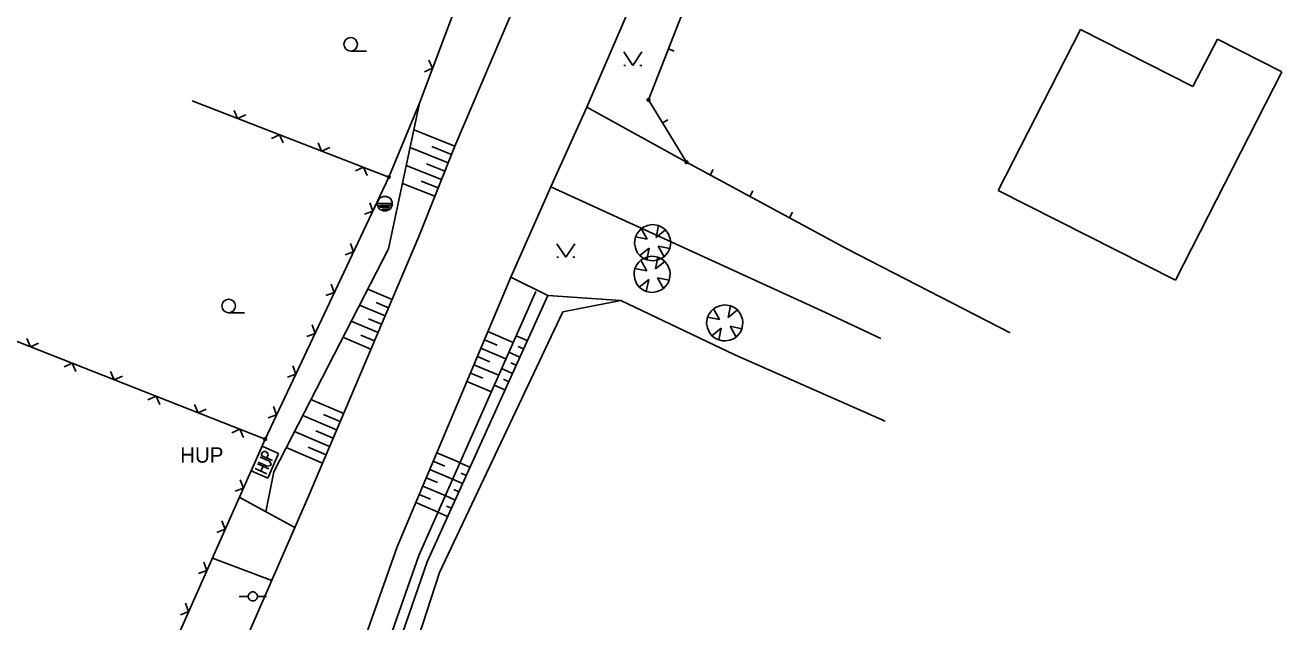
# Model space of a CAD drawing. Extents: x -559554 to -559082, y -1075950 to -1075150.
# Drawn here: x -559203.9 to -559134.2, y -1075319.9 to -1075286.8 of the extents above; entities that cross this region are included whole.
import ezdxf

# ---------------------------------------------------------------- set-up
doc = ezdxf.new("R2010")
doc.units = 0
doc.layers.add('kl', color=7, linetype='Continuous')
doc.layers.add('PF', color=7, linetype='Continuous')

msp = doc.modelspace()

# ---------------------------------------------------------------- linework, layer by layer
at = {"layer": 'kl'}
for p, q in [((-559182.05, -1075291.08), (-559175.25, -1075273.02)), ((-559180.09, -1075293.47), (-559173.73, -1075278.55)), ((-559172.77, -1075291.32), (-559167.67, -1075279.49)), ((-559164.97, -1075279.68), (-559169.34, -1075290.91)), ((-559185.866, -1075288.195), (-559184.991, -1075288.195)), ((-559170.716, -1075288.24), (-559170.216, -1075288.99)), ((-559170.216, -1075288.99), (-559169.716, -1075288.24)), ((-559168.233, -1075288.067), (-559167.907, -1075288.194)), ((-559181.323, -1075289.149), (-559181.527, -1075288.698)), ((-559170.716, -1075288.99), (-559170.616, -1075288.99)), ((-559169.816, -1075288.99), (-559169.716, -1075288.99)), ((-559181.773, -1075289.353), (-559181.323, -1075289.149)), ((-559183.75, -1075295.19), (-559194.672, -1075290.966)), ((-559183.77, -1075299.18), (-559182.05, -1075291.08)), ((-559183.75, -1075295.19), (-559182.05, -1075291.08)), ((-559169.395, -1075290.909), (-559169.384, -1075290.887)), ((-559169.306, -1075290.955), (-559169.395, -1075290.909)), ((-559169.385, -1075290.943), (-559169.34, -1075290.966)), ((-559169.384, -1075290.887), (-559169.295, -1075290.932)), ((-559169.372, -1075290.865), (-559169.339, -1075290.854)), ((-559169.283, -1075290.91), (-559169.372, -1075290.865)), ((-559169.34, -1075290.91), (-559167.23, -1075294.37)), ((-559169.34, -1075290.966), (-559169.306, -1075290.955)), ((-559169.339, -1075290.854), (-559169.294, -1075290.877)), ((-559169.295, -1075290.932), (-559169.283, -1075290.91)), ((-559192.344, -1075291.491), (-559192.144, -1075291.943)), ((-559192.144, -1075291.943), (-559191.691, -1075291.743)), ((-559174.76, -1075295.73), (-559172.77, -1075291.32)), ((-559167.23, -1075294.37), (-559172.77, -1075291.32)), ((-559168.559, -1075292.19), (-559168.26, -1075292.008)), ((-559189.812, -1075292.845), (-559190.265, -1075293.045)), ((-559189.612, -1075293.298), (-559189.812, -1075292.845)), ((-559180.09, -1075293.47), (-559182.365, -1075292.563)), ((-559187.68, -1075293.294), (-559187.48, -1075293.747)), ((-559187.48, -1075293.747), (-559187.028, -1075293.547)), ((-559180.46, -1075294.398), (-559182.575, -1075293.556)), ((-559182.09, -1075298.49), (-559180.09, -1075293.47)), ((-559180.275, -1075293.934), (-559181.372, -1075293.497)), ((-559180.83, -1075295.327), (-559182.786, -1075294.548)), ((-559180.645, -1075294.863), (-559181.663, -1075294.457)), ((-559167.285, -1075294.369), (-559167.274, -1075294.347)), ((-559167.196, -1075294.415), (-559167.285, -1075294.369)), ((-559167.275, -1075294.403), (-559167.23, -1075294.426)), ((-559167.274, -1075294.347), (-559167.185, -1075294.392)), ((-559167.262, -1075294.325), (-559167.229, -1075294.314)), ((-559167.173, -1075294.37), (-559167.262, -1075294.325)), ((-559167.23, -1075294.37), (-559158.29, -1075299.19)), ((-559167.23, -1075294.426), (-559167.196, -1075294.415)), ((-559167.229, -1075294.314), (-559167.184, -1075294.337)), ((-559167.185, -1075294.392), (-559167.173, -1075294.37)), ((-559190.62, -1075309.75), (-559183.75, -1075295.19)), ((-559185.149, -1075294.648), (-559185.601, -1075294.849)), ((-559184.948, -1075295.101), (-559185.149, -1075294.648)), ((-559183.805, -1075295.189), (-559183.794, -1075295.167)), ((-559183.716, -1075295.235), (-559183.805, -1075295.189)), ((-559183.795, -1075295.223), (-559183.75, -1075295.246)), ((-559183.794, -1075295.167), (-559183.705, -1075295.212)), ((-559183.782, -1075295.145), (-559183.749, -1075295.134)), ((-559183.693, -1075295.19), (-559183.782, -1075295.145)), ((-559183.75, -1075295.246), (-559183.716, -1075295.235)), ((-559183.749, -1075295.134), (-559183.704, -1075295.157)), ((-559183.705, -1075295.212), (-559183.693, -1075295.19)), ((-559165.909, -1075295.081), (-559165.743, -1075294.773)), ((-559181.2, -1075296.256), (-559182.997, -1075295.541)), ((-559181.015, -1075295.792), (-559181.953, -1075295.418)), ((-559176.98, -1075300.76), (-559174.76, -1075295.73)), ((-559159.52, -1075302.72), (-559174.76, -1075295.73)), ((-559163.709, -1075296.268), (-559163.543, -1075295.96)), ((-559184.645, -1075297.088), (-559184.813, -1075296.622)), ((-559184.374, -1075296.569), (-559184.274, -1075296.369)), ((-559184.374, -1075296.769), (-559184.374, -1075296.569)), ((-559184.374, -1075296.669), (-559183.574, -1075296.669)), ((-559184.274, -1075296.369), (-559184.074, -1075296.269)), ((-559184.074, -1075296.269), (-559183.874, -1075296.269)), ((-559183.874, -1075296.269), (-559183.674, -1075296.369)), ((-559183.674, -1075296.369), (-559183.574, -1075296.569)), ((-559183.574, -1075296.669), (-559183.674, -1075296.769)), ((-559183.574, -1075296.569), (-559183.574, -1075296.769)), ((-559185.111, -1075297.255), (-559184.645, -1075297.088)), ((-559184.274, -1075296.969), (-559184.374, -1075296.769)), ((-559183.674, -1075296.769), (-559184.274, -1075296.769)), ((-559184.274, -1075296.769), (-559184.224, -1075296.869)), ((-559184.074, -1075297.069), (-559184.274, -1075296.969)), ((-559184.224, -1075296.869), (-559183.724, -1075296.869)), ((-559183.824, -1075296.969), (-559184.124, -1075296.969)), ((-559183.874, -1075297.069), (-559184.074, -1075297.069)), ((-559183.674, -1075296.969), (-559183.874, -1075297.069)), ((-559183.724, -1075296.869), (-559183.824, -1075296.969)), ((-559183.574, -1075296.769), (-559183.674, -1075296.969)), ((-559161.508, -1075297.454), (-559161.342, -1075297.146)), ((-559169.848, -1075298.171), (-559169.74, -1075298.055)), ((-559169.74, -1075298.055), (-559169.587, -1075297.961)), ((-559169.407, -1075298.648), (-559169.74, -1075298.055)), ((-559169.587, -1075297.961), (-559169.388, -1075297.887)), ((-559169.388, -1075297.887), (-559169.143, -1075297.834)), ((-559169.143, -1075297.834), (-559168.986, -1075297.851)), ((-559168.986, -1075297.851), (-559168.784, -1075297.889)), ((-559168.784, -1075297.889), (-559168.918, -1075298.542)), ((-559168.918, -1075298.542), (-559168.395, -1075298.122)), ((-559168.784, -1075297.889), (-559168.602, -1075297.972)), ((-559168.602, -1075297.972), (-559168.395, -1075298.122)), ((-559168.395, -1075298.122), (-559168.231, -1075298.362)), ((-559188.19, -1075312.87), (-559182.09, -1075298.49)), ((-559170.115, -1075298.873), (-559170.098, -1075298.716)), ((-559170.098, -1075298.716), (-559170.06, -1075298.514)), ((-559170.06, -1075298.514), (-559169.977, -1075298.332)), ((-559170.06, -1075298.514), (-559169.407, -1075298.648)), ((-559169.977, -1075298.332), (-559169.848, -1075298.171)), ((-559168.231, -1075298.362), (-559168.132, -1075298.628)), ((-559168.132, -1075298.628), (-559168.104, -1075298.806)), ((-559168.104, -1075298.806), (-559168.121, -1075298.963)), ((-559190.14, -1075311.56), (-559183.77, -1075299.18)), ((-559186.178, -1075299.516), (-559185.712, -1075299.349)), ((-559185.712, -1075299.349), (-559185.879, -1075298.883)), ((-559174.432, -1075298.891), (-559173.932, -1075299.641)), ((-559173.932, -1075299.641), (-559173.432, -1075298.891)), ((-559170.062, -1075299.118), (-559170.115, -1075298.873)), ((-559169.964, -1075299.383), (-559170.062, -1075299.118)), ((-559169.824, -1075299.557), (-559169.964, -1075299.383)), ((-559169.824, -1075299.557), (-559169.301, -1075299.137)), ((-559169.301, -1075299.137), (-559169.436, -1075299.79)), ((-559168.159, -1075299.166), (-559168.812, -1075299.031)), ((-559168.812, -1075299.031), (-559168.479, -1075299.624)), ((-559168.371, -1075299.508), (-559168.479, -1075299.624)), ((-559168.242, -1075299.347), (-559168.371, -1075299.508)), ((-559168.159, -1075299.166), (-559168.242, -1075299.347)), ((-559168.121, -1075298.963), (-559168.159, -1075299.166)), ((-559158.29, -1075299.19), (-559149.274, -1075303.836)), ((-559174.432, -1075299.641), (-559174.332, -1075299.641)), ((-559173.532, -1075299.641), (-559173.432, -1075299.641)), ((-559170.09, -1075300.264), (-559170.007, -1075300.082)), ((-559170.007, -1075300.082), (-559169.878, -1075299.921)), ((-559169.878, -1075299.921), (-559169.77, -1075299.805)), ((-559169.617, -1075299.707), (-559169.824, -1075299.557)), ((-559169.77, -1075299.805), (-559169.617, -1075299.711)), ((-559169.437, -1075300.398), (-559169.77, -1075299.805)), ((-559169.617, -1075299.711), (-559169.418, -1075299.637)), ((-559169.436, -1075299.79), (-559169.617, -1075299.707)), ((-559169.233, -1075299.828), (-559169.436, -1075299.79)), ((-559169.418, -1075299.637), (-559169.173, -1075299.584)), ((-559169.076, -1075299.845), (-559169.233, -1075299.828)), ((-559169.173, -1075299.584), (-559169.016, -1075299.601)), ((-559168.831, -1075299.792), (-559169.076, -1075299.845)), ((-559169.016, -1075299.601), (-559168.814, -1075299.639)), ((-559168.814, -1075299.639), (-559168.948, -1075300.292)), ((-559168.948, -1075300.292), (-559168.425, -1075299.872)), ((-559168.632, -1075299.718), (-559168.831, -1075299.792)), ((-559168.814, -1075299.639), (-559168.632, -1075299.722)), ((-559168.479, -1075299.624), (-559168.632, -1075299.718)), ((-559168.632, -1075299.722), (-559168.425, -1075299.872)), ((-559168.425, -1075299.872), (-559168.261, -1075300.112)), ((-559168.261, -1075300.112), (-559168.162, -1075300.378)), ((-559183.29, -1075315.72), (-559176.98, -1075300.76)), ((-559174.93, -1075301.76), (-559176.98, -1075300.76)), ((-559170.145, -1075300.623), (-559170.128, -1075300.466)), ((-559170.092, -1075300.868), (-559170.145, -1075300.623)), ((-559170.128, -1075300.466), (-559170.09, -1075300.264)), ((-559169.994, -1075301.133), (-559170.092, -1075300.868)), ((-559170.09, -1075300.264), (-559169.437, -1075300.398)), ((-559169.854, -1075301.307), (-559169.331, -1075300.887)), ((-559169.331, -1075300.887), (-559169.466, -1075301.54)), ((-559168.189, -1075300.916), (-559168.842, -1075300.781)), ((-559168.842, -1075300.781), (-559168.509, -1075301.374)), ((-559168.151, -1075300.713), (-559168.189, -1075300.916)), ((-559168.162, -1075300.378), (-559168.134, -1075300.556)), ((-559168.134, -1075300.556), (-559168.151, -1075300.713)), ((-559187.245, -1075301.777), (-559186.779, -1075301.61)), ((-559186.779, -1075301.61), (-559186.946, -1075301.144)), ((-559183.572, -1075301.985), (-559184.919, -1075301.414)), ((-559182.09, -1075316.2), (-559175.59, -1075301.54)), ((-559169.854, -1075301.307), (-559169.994, -1075301.133)), ((-559169.647, -1075301.457), (-559169.854, -1075301.307)), ((-559169.466, -1075301.54), (-559169.647, -1075301.457)), ((-559169.263, -1075301.578), (-559169.466, -1075301.54)), ((-559169.106, -1075301.595), (-559169.263, -1075301.578)), ((-559168.861, -1075301.542), (-559169.106, -1075301.595)), ((-559168.662, -1075301.468), (-559168.861, -1075301.542)), ((-559168.509, -1075301.374), (-559168.662, -1075301.468)), ((-559168.401, -1075301.258), (-559168.509, -1075301.374)), ((-559168.272, -1075301.097), (-559168.401, -1075301.258)), ((-559168.189, -1075300.916), (-559168.272, -1075301.097)), ((-559183.963, -1075302.906), (-559185.378, -1075302.306)), ((-559183.768, -1075302.446), (-559184.458, -1075302.153)), ((-559181.63, -1075316.56), (-559174.93, -1075301.76)), ((-559174.93, -1075301.76), (-559170.88, -1075302.04)), ((-559174.09, -1075302.67), (-559170.88, -1075302.04)), ((-559170.88, -1075302.04), (-559164.55, -1075305.06)), ((-559165.388, -1075302.337), (-559165.143, -1075302.284)), ((-559165.143, -1075302.284), (-559164.986, -1075302.301)), ((-559164.986, -1075302.301), (-559164.784, -1075302.339)), ((-559192.642, -1075302.723), (-559191.767, -1075302.723)), ((-559180.94, -1075317.16), (-559174.09, -1075302.67)), ((-559166.098, -1075303.166), (-559166.06, -1075302.964)), ((-559166.06, -1075302.964), (-559165.977, -1075302.782)), ((-559166.06, -1075302.964), (-559165.407, -1075303.098)), ((-559165.977, -1075302.782), (-559165.848, -1075302.621)), ((-559165.848, -1075302.621), (-559165.74, -1075302.505)), ((-559165.74, -1075302.505), (-559165.587, -1075302.411)), ((-559165.407, -1075303.098), (-559165.74, -1075302.505)), ((-559165.587, -1075302.411), (-559165.388, -1075302.337)), ((-559164.784, -1075302.339), (-559164.918, -1075302.992)), ((-559164.918, -1075302.992), (-559164.395, -1075302.572)), ((-559164.784, -1075302.339), (-559164.602, -1075302.422)), ((-559164.602, -1075302.422), (-559164.395, -1075302.572)), ((-559164.395, -1075302.572), (-559164.231, -1075302.812)), ((-559164.231, -1075302.812), (-559164.132, -1075303.078)), ((-559159.52, -1075302.72), (-559156.454, -1075304.164)), ((-559190.62, -1075309.75), (-559207.515, -1075303.095)), ((-559187.846, -1075303.871), (-559188.013, -1075303.405)), ((-559184.353, -1075303.827), (-559185.837, -1075303.197)), ((-559184.158, -1075303.366), (-559184.883, -1075303.059)), ((-559166.115, -1075303.323), (-559166.098, -1075303.166)), ((-559166.062, -1075303.568), (-559166.115, -1075303.323)), ((-559165.964, -1075303.833), (-559166.062, -1075303.568)), ((-559165.824, -1075304.007), (-559165.301, -1075303.587)), ((-559165.301, -1075303.587), (-559165.436, -1075304.24)), ((-559164.159, -1075303.616), (-559164.812, -1075303.481)), ((-559164.812, -1075303.481), (-559164.479, -1075304.074)), ((-559164.159, -1075303.616), (-559164.242, -1075303.797)), ((-559164.121, -1075303.413), (-559164.159, -1075303.616)), ((-559164.132, -1075303.078), (-559164.104, -1075303.256)), ((-559164.104, -1075303.256), (-559164.121, -1075303.413)), ((-559203.843, -1075304.165), (-559203.645, -1075304.619)), ((-559188.312, -1075304.038), (-559187.846, -1075303.871)), ((-559184.744, -1075304.747), (-559186.296, -1075304.089)), ((-559184.549, -1075304.287), (-559185.307, -1075303.965)), ((-559178.447, -1075304.238), (-559177.747, -1075304.533)), ((-559178.252, -1075303.777), (-559176.845, -1075304.371)), ((-559176.069, -1075304.277), (-559176.681, -1075304)), ((-559165.824, -1075304.007), (-559165.964, -1075303.833)), ((-559165.617, -1075304.157), (-559165.824, -1075304.007)), ((-559165.436, -1075304.24), (-559165.617, -1075304.157)), ((-559165.233, -1075304.278), (-559165.436, -1075304.24)), ((-559165.076, -1075304.295), (-559165.233, -1075304.278)), ((-559164.831, -1075304.242), (-559165.076, -1075304.295)), ((-559164.632, -1075304.168), (-559164.831, -1075304.242)), ((-559164.479, -1075304.074), (-559164.632, -1075304.168)), ((-559164.371, -1075303.958), (-559164.479, -1075304.074)), ((-559164.242, -1075303.797), (-559164.371, -1075303.958)), ((-559203.645, -1075304.619), (-559203.192, -1075304.421)), ((-559178.641, -1075304.699), (-559177.25, -1075305.285)), ((-559176.482, -1075305.188), (-559177.086, -1075304.914)), ((-559176.275, -1075304.733), (-559176.579, -1075304.595)), ((-559164.55, -1075305.06), (-559156.203, -1075308.739)), ((-559201.319, -1075305.535), (-559201.773, -1075305.732)), ((-559201.122, -1075305.989), (-559201.319, -1075305.535)), ((-559188.913, -1075306.132), (-559189.08, -1075305.666)), ((-559179.03, -1075305.62), (-559177.656, -1075306.2)), ((-559178.835, -1075305.16), (-559178.144, -1075305.451)), ((-559176.688, -1075305.644), (-559176.988, -1075305.508)), ((-559199.191, -1075305.997), (-559198.993, -1075306.451)), ((-559198.993, -1075306.451), (-559198.539, -1075306.254)), ((-559189.379, -1075306.299), (-559188.913, -1075306.132)), ((-559179.224, -1075306.081), (-559178.541, -1075306.369)), ((-559176.894, -1075306.099), (-559177.491, -1075305.829)), ((-559177.1, -1075306.555), (-559177.397, -1075306.42)), ((-559179.418, -1075306.542), (-559178.061, -1075307.114)), ((-559177.306, -1075307.01), (-559177.897, -1075306.743)), ((-559196.667, -1075307.367), (-559197.121, -1075307.565)), ((-559196.47, -1075307.821), (-559196.667, -1075307.367)), ((-559194.539, -1075307.83), (-559194.341, -1075308.284)), ((-559186.257, -1075308.315), (-559188.073, -1075307.544)), ((-559194.341, -1075308.284), (-559193.887, -1075308.086)), ((-559190.445, -1075308.56), (-559189.979, -1075308.393)), ((-559189.979, -1075308.393), (-559190.147, -1075307.927)), ((-559186.648, -1075309.235), (-559188.532, -1075308.436)), ((-559186.453, -1075308.775), (-559187.378, -1075308.382)), ((-559192.015, -1075309.2), (-559192.469, -1075309.397)), ((-559191.818, -1075309.654), (-559192.015, -1075309.2)), ((-559195.47, -1075320.69), (-559190.62, -1075309.75)), ((-559190.675, -1075309.749), (-559190.664, -1075309.727)), ((-559190.586, -1075309.795), (-559190.675, -1075309.749)), ((-559190.665, -1075309.783), (-559190.62, -1075309.806)), ((-559190.664, -1075309.727), (-559190.575, -1075309.772)), ((-559190.652, -1075309.705), (-559190.619, -1075309.694)), ((-559190.563, -1075309.75), (-559190.652, -1075309.705)), ((-559190.62, -1075309.806), (-559190.586, -1075309.795)), ((-559190.619, -1075309.694), (-559190.574, -1075309.717)), ((-559190.575, -1075309.772), (-559190.563, -1075309.75)), ((-559187.038, -1075310.156), (-559188.991, -1075309.327)), ((-559186.843, -1075309.695), (-559187.802, -1075309.289)), ((-559191.389, -1075311.505), (-559190.781, -1075310.134)), ((-559190.846, -1075310.652), (-559190.765, -1075310.469)), ((-559190.206, -1075310.936), (-559190.846, -1075310.652)), ((-559190.781, -1075310.134), (-559189.867, -1075310.539)), ((-559190.765, -1075310.469), (-559190.633, -1075310.418)), ((-559190.633, -1075310.418), (-559190.496, -1075310.479)), ((-559190.445, -1075310.611), (-559190.526, -1075310.794)), ((-559190.496, -1075310.479), (-559190.445, -1075310.611)), ((-559189.867, -1075310.539), (-559190.475, -1075311.911)), ((-559187.429, -1075311.076), (-559189.45, -1075310.219)), ((-559187.234, -1075310.616), (-559188.227, -1075310.195)), ((-559181.092, -1075310.509), (-559179.807, -1075311.051)), ((-559190.409, -1075311.393), (-559191.049, -1075311.109)), ((-559191.008, -1075311.018), (-559190.506, -1075311.241)), ((-559190.384, -1075310.966), (-559190.887, -1075310.743)), ((-559190.851, -1075311.525), (-559190.729, -1075311.251)), ((-559190.506, -1075311.241), (-559190.394, -1075311.235)), ((-559190.394, -1075311.235), (-559190.328, -1075311.21)), ((-559190.313, -1075311.053), (-559190.384, -1075310.966)), ((-559190.328, -1075311.21), (-559190.287, -1075311.119)), ((-559190.287, -1075311.119), (-559190.313, -1075311.053)), ((-559181.286, -1075310.97), (-559180.648, -1075311.239)), ((-559179.251, -1075311.306), (-559179.808, -1075311.053)), ((-559191.822, -1075312.462), (-559192, -1075312)), ((-559190.475, -1075311.911), (-559191.389, -1075311.505)), ((-559191.171, -1075311.383), (-559190.531, -1075311.667)), ((-559190.574, -1075313.774), (-559190.14, -1075311.56)), ((-559181.675, -1075311.891), (-559181.045, -1075312.157)), ((-559181.48, -1075311.43), (-559180.212, -1075311.965)), ((-559179.663, -1075312.217), (-559180.213, -1075311.968)), ((-559179.457, -1075311.761), (-559179.734, -1075311.636)), ((-559192.284, -1075312.64), (-559191.822, -1075312.462)), ((-559181.869, -1075312.352), (-559180.618, -1075312.88)), ((-559179.87, -1075312.672), (-559180.143, -1075312.548)), ((-559192.2, -1075322.07), (-559188.19, -1075312.87)), ((-559192.05, -1075312.976), (-559188.963, -1075314.644)), ((-559182.258, -1075313.273), (-559181.023, -1075313.794)), ((-559182.063, -1075312.812), (-559181.442, -1075313.075)), ((-559180.076, -1075313.128), (-559180.619, -1075312.882)), ((-559180.282, -1075313.583), (-559180.552, -1075313.461)), ((-559180.488, -1075314.039), (-559181.024, -1075313.796)), ((-559193.297, -1075314.925), (-559192.835, -1075314.747)), ((-559192.835, -1075314.747), (-559193.013, -1075314.285)), ((-559190.12, -1075334.97), (-559183.29, -1075315.72)), ((-559188.81, -1075335.32), (-559182.09, -1075316.2)), ((-559193.848, -1075317.033), (-559194.026, -1075316.571)), ((-559193.545, -1075316.348), (-559190.253, -1075317.603)), ((-559188.13, -1075335.39), (-559181.63, -1075316.56)), ((-559194.31, -1075317.211), (-559193.848, -1075317.033)), ((-559186.99, -1075335.7), (-559180.94, -1075317.16)), ((-559191.55, -1075318.43), (-559191.5, -1075318.33)), ((-559191.5, -1075318.33), (-559191.45, -1075318.28)), ((-559191.45, -1075318.28), (-559191.35, -1075318.23)), ((-559191.35, -1075318.23), (-559191.25, -1075318.23)), ((-559191.25, -1075318.23), (-559191.15, -1075318.28)), ((-559191.15, -1075318.28), (-559191.1, -1075318.33)), ((-559191.1, -1075318.33), (-559191.05, -1075318.43)), ((-559194.862, -1075319.318), (-559195.04, -1075318.856)), ((-559192.05, -1075318.48), (-559191.55, -1075318.48)), ((-559191.55, -1075318.53), (-559191.55, -1075318.43)), ((-559191.5, -1075318.63), (-559191.55, -1075318.53)), ((-559191.45, -1075318.68), (-559191.5, -1075318.63)), ((-559191.35, -1075318.73), (-559191.45, -1075318.68)), ((-559191.25, -1075318.73), (-559191.35, -1075318.73)), ((-559191.15, -1075318.68), (-559191.25, -1075318.73)), ((-559191.1, -1075318.63), (-559191.15, -1075318.68)), ((-559191.05, -1075318.53), (-559191.1, -1075318.63)), ((-559191.05, -1075318.43), (-559191.05, -1075318.53)), ((-559191.05, -1075318.48), (-559190.55, -1075318.48)), ((-559195.323, -1075319.496), (-559194.862, -1075319.318))]:
    msp.add_line(p, q, dxfattribs=at)
for centre, radius in [((-559185.866, -1075287.82), 0.375), ((-559169.34, -1075290.91), 0.075), ((-559167.23, -1075294.37), 0.075), ((-559183.75, -1075295.19), 0.075), ((-559192.643, -1075302.349), 0.375), ((-559190.62, -1075309.75), 0.075)]:
    msp.add_circle(centre, radius, dxfattribs=at)
at = {"layer": 'PF'}
for p, q in [((-559145.359, -1075286.999), (-559149.93, -1075295.939)), ((-559145.359, -1075286.999), (-559139.129, -1075290.169)), ((-559137.77, -1075287.529), (-559139.129, -1075290.169)), ((-559137.77, -1075287.529), (-559134.189, -1075289.349)), ((-559134.189, -1075289.349), (-559140.099, -1075300.91)), ((-559149.93, -1075295.939), (-559140.099, -1075300.91))]:
    msp.add_line(p, q, dxfattribs=at)

# ---------------------------------------------------------------- texts
at = {"layer": 'kl'}
msp.add_text('HUP', height=0.85, dxfattribs=at).set_placement((-559195.33, -1075311.051))

doc.saveas('drawing.dxf')
